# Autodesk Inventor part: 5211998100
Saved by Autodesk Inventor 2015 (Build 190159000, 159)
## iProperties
Created: 2020-07
Part Number: 5211998100
Checked By: TraceParts S.A.
Material: Generic
Catalog Web Link: www.traceparts.com
Document SubType Name: Modeling
Designer: TraceParts
Density: 1 g/cm^3
Appearance: Default
Company: TraceParts S.A.
Author: TraceParts
REFERENCE: 5211998100
DESIGN: TDM-100 (127V 60) BRA RZ - 5211998100
SUPPLIER: Soler & Palau
TraceParts.PartNumber: 10-20122018-119657
TraceParts.PartTitle: TDM
TraceParts.InstanceId: 10-20122018-119657ETRHOXTGVHE6XQT6NOOYWAISS
TraceParts.PartStatus: Published
TraceParts.PartVersion: 1.0.2
TRACEPARTS: TRACEPARTS
TraceParts.PartLanguage: en
TraceParts.ClassPath: SOLER_PALAU:10-20122018-119657
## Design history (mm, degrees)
feature "5211998100"
body "Solid1"
